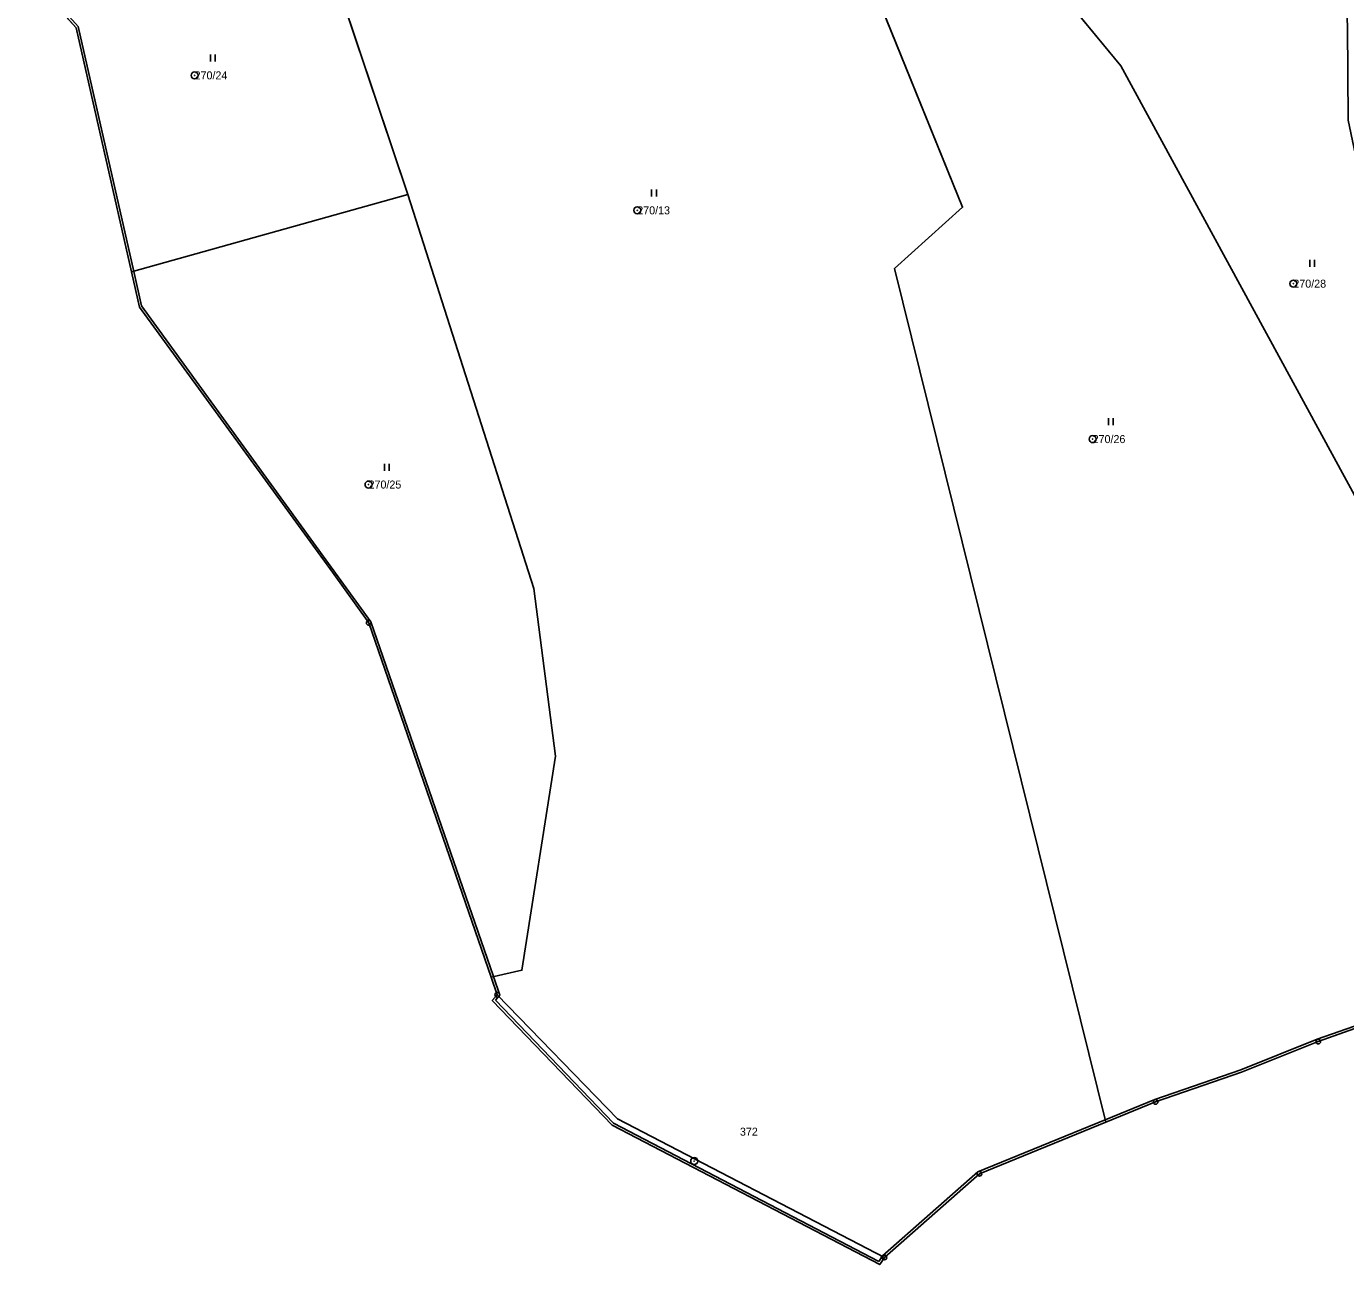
# Model space of a CAD drawing. Extents: x -652854 to -650068, y -1097661 to -1095417.
# Drawn here: x -652221.5 to -651941.1, y -1096457.9 to -1096194.7 of the extents above; entities that cross this region are included whole.
import ezdxf

# ---------------------------------------------------------------- set-up
doc = ezdxf.new("R2010")
doc.units = 0
for name, color, linetype in [('Definiční body parcel', 7, 'Continuous'), ('Geodetické body', 7, 'Continuous'), ('Hranice obcí', 7, 'Continuous'), ('Hranice parcel', 7, 'Continuous'), ('Obvody jako plochy', 7, 'Continuous'), ('Ostatní hranice', 7, 'Continuous'), ('Parcelní čísla', 7, 'Continuous'), ('Prvky pro prodl_ par_ č_', 7, 'Continuous'), ('Značky kultur', 7, 'Continuous')]:
    doc.layers.add(name, color=color, linetype=linetype)

msp = doc.modelspace()

# ---------------------------------------------------------------- linework, layer by layer
at = {"layer": 'Definiční body parcel'}
for centre, radius in [((-652185.7, -1096205.16), 0.75), ((-652185.7, -1096205.16), 0.0327), ((-652091.65, -1096233.84), 0.75), ((-652091.65, -1096233.84), 0.0327), ((-651952.24, -1096249.42), 0.75), ((-651952.24, -1096249.42), 0.0327), ((-651994.89, -1096282.46), 0.75), ((-651994.89, -1096282.46), 0.0327), ((-652148.74, -1096292.12), 0.75), ((-652148.74, -1096292.12), 0.0327), ((-652079.55, -1096435.9), 0.75), ((-652079.55, -1096435.9), 0.0327)]:
    msp.add_circle(centre, radius, dxfattribs=at)
at = {"layer": 'Geodetické body'}
for centre, radius in [((-652148.71, -1096321.51), 0.5), ((-652148.71, -1096321.51), 0.001), ((-652121.39, -1096400.54), 0.5), ((-652121.39, -1096400.54), 0.001), ((-651946.95, -1096410.49), 0.5), ((-651946.95, -1096410.49), 0.001), ((-651981.51, -1096423.32), 0.5), ((-651981.51, -1096423.32), 0.001), ((-652018.96, -1096438.6), 0.5), ((-652018.96, -1096438.6), 0.001), ((-652039.13, -1096456.38), 0.5), ((-652039.13, -1096456.38), 0.001)]:
    msp.add_circle(centre, radius, dxfattribs=at)
at = {"layer": 'Hranice obcí'}
for p, q in [((-652210.9, -1096195.04), (-652221.45, -1096183.25)), ((-652199.14, -1096246.92), (-652210.9, -1096195.04)), ((-652197.44, -1096254.42), (-652199.14, -1096246.92)), ((-652156.44, -1096310.73), (-652197.44, -1096254.42)), ((-652148.71, -1096321.51), (-652156.44, -1096310.73)), ((-652122.68, -1096396.82), (-652148.71, -1096321.51)), ((-652121.39, -1096400.54), (-652122.68, -1096396.82)), ((-652122.45, -1096401.76), (-652121.39, -1096400.54)), ((-651915.68, -1096399.4), (-651946.95, -1096410.49)), ((-652096.98, -1096428.27), (-652122.45, -1096401.76)), ((-651946.95, -1096410.49), (-651963.26, -1096417)), ((-651963.26, -1096417), (-651981.51, -1096423.32)), ((-651981.51, -1096423.32), (-651992.07, -1096427.63)), ((-652040.14, -1096457.91), (-652096.98, -1096428.27)), ((-651992.07, -1096427.63), (-652018.96, -1096438.6)), ((-652018.96, -1096438.6), (-652039.13, -1096456.38)), ((-652039.13, -1096456.38), (-652040.14, -1096457.91))]:
    msp.add_line(p, q, dxfattribs=at)
at = {"layer": 'Hranice parcel'}
for p, q in [((-652057.53, -1096119.89), (-651988.88, -1096203.13)), ((-652066.96, -1096123.51), (-652022.53, -1096233.18)), ((-652163.72, -1096161.03), (-652140.38, -1096230.48)), ((-651988.88, -1096203.13), (-651935.29, -1096301.66)), ((-652140.38, -1096230.48), (-652199.14, -1096246.92)), ((-652140.38, -1096230.48), (-652113.66, -1096314.2)), ((-652022.53, -1096233.18), (-652036.99, -1096246.19)), ((-652036.99, -1096246.19), (-651992.07, -1096427.63)), ((-652113.66, -1096314.2), (-652109.04, -1096349.86)), ((-652109.04, -1096349.86), (-652116.16, -1096395.34)), ((-652116.16, -1096395.34), (-652122.68, -1096396.82)), ((-652121.39, -1096400.54), (-652095.82, -1096426.92)), ((-652095.82, -1096426.92), (-652039.13, -1096456.38))]:
    msp.add_line(p, q, dxfattribs=at)
at = {"layer": 'Obvody jako plochy'}
for points in [[(-652047.62, -1096116.05), (-652057.53, -1096119.89), (-651988.88, -1096203.13), (-651935.29, -1096301.66), (-651889.71, -1096389.26), (-651881.07, -1096385.89), (-651862.37, -1096368.4), (-651859.22, -1096330.24), (-651863.16, -1096325.62), (-651893.8, -1096290.17), (-651915.5, -1096264.18), (-651935.12, -1096240.7), (-651940.57, -1096214.69), (-651940.73, -1096194.74), (-651941.55, -1096176.41), (-651982.15, -1096156.91), (-652010.08, -1096146.47), (-652028.17, -1096124.39)], [(-652057.53, -1096119.89), (-652066.96, -1096123.51), (-652022.53, -1096233.18), (-652036.99, -1096246.19), (-651992.07, -1096427.63), (-651981.51, -1096423.32), (-651963.26, -1096417), (-651946.95, -1096410.49), (-651915.68, -1096399.4), (-651889.71, -1096389.26), (-651935.29, -1096301.66), (-651988.88, -1096203.13)], [(-652066.96, -1096123.51), (-652163.72, -1096161.03), (-652140.38, -1096230.48), (-652113.66, -1096314.2), (-652109.04, -1096349.86), (-652116.16, -1096395.34), (-652122.68, -1096396.82), (-652121.39, -1096400.54), (-652095.82, -1096426.92), (-652039.13, -1096456.38), (-652018.96, -1096438.6), (-651992.07, -1096427.63), (-652036.99, -1096246.19), (-652022.53, -1096233.18)], [(-652163.72, -1096161.03), (-652221.45, -1096183.25), (-652210.9, -1096195.04), (-652199.14, -1096246.92), (-652140.38, -1096230.48)], [(-652197.44, -1096254.42), (-652156.44, -1096310.73), (-652148.71, -1096321.51), (-652122.68, -1096396.82), (-652116.16, -1096395.34), (-652109.04, -1096349.86), (-652113.66, -1096314.2), (-652140.38, -1096230.48), (-652199.14, -1096246.92)], [(-652121.39, -1096400.54), (-652122.45, -1096401.76), (-652096.98, -1096428.27), (-652040.14, -1096457.91), (-652039.13, -1096456.38), (-652095.82, -1096426.92)]]:
    msp.add_lwpolyline(points, close=True, dxfattribs=at)
at = {"layer": 'Ostatní hranice'}
for p, q in [((-652210.48, -1096194.75), (-652221.05, -1096182.93)), ((-652198.64, -1096246.85), (-652210.48, -1096194.75)), ((-652197, -1096254.17), (-652198.64, -1096246.85)), ((-652148.26, -1096321.27), (-652197, -1096254.17)), ((-652122.2, -1096396.66), (-652148.26, -1096321.27)), ((-652120.86, -1096400.61), (-652122.2, -1096396.66)), ((-651915.84, -1096398.91), (-651947.15, -1096410.02)), ((-652121.78, -1096401.74), (-652120.86, -1096400.61)), ((-652096.68, -1096427.86), (-652121.78, -1096401.74)), ((-651947.15, -1096410.02), (-651963.43, -1096416.53)), ((-651963.43, -1096416.53), (-651981.7, -1096422.85)), ((-651981.7, -1096422.85), (-651992.26, -1096427.17)), ((-652040.32, -1096457.25), (-652096.68, -1096427.86)), ((-651992.26, -1096427.17), (-652019.26, -1096438.19)), ((-652019.26, -1096438.19), (-652039.51, -1096456.04)), ((-652039.51, -1096456.04), (-652040.32, -1096457.25))]:
    msp.add_line(p, q, dxfattribs=at)
at = {"layer": 'Značky kultur'}
for p, q in [((-652182.357, -1096200.725), (-652182.357, -1096202.225)), ((-652181.335, -1096202.225), (-652181.335, -1096200.725)), ((-652088.607, -1096229.405), (-652088.607, -1096230.905)), ((-652087.585, -1096230.905), (-652087.585, -1096229.405)), ((-651948.767, -1096244.365), (-651948.767, -1096245.865)), ((-651947.745, -1096245.865), (-651947.745, -1096244.365)), ((-651991.547, -1096278.025), (-651991.547, -1096279.525)), ((-651990.525, -1096279.525), (-651990.525, -1096278.025)), ((-652145.357, -1096287.685), (-652145.357, -1096289.185)), ((-652144.335, -1096289.185), (-652144.335, -1096287.685))]:
    msp.add_line(p, q, dxfattribs=at)

# ---------------------------------------------------------------- texts
at = {"layer": 'Parcelní čísla'}
for s, height, p in [('270/24', 1.7, (-652185.7, -1096206.01)), ('270/13', 1.7, (-652091.65, -1096234.69)), ('270/28', 1.7, (-651952.24, -1096250.27)), ('270/26', 1.7, (-651994.89, -1096283.31)), ('270/25', 1.7, (-652148.74, -1096292.97)), ('372', 0.1, (-652079.55, -1096435.9))]:
    msp.add_text(s, height=height, dxfattribs=at).set_placement(p)
at = {"layer": 'Prvky pro prodl_ par_ č_'}
msp.add_text('372', height=1.7, dxfattribs=at).set_placement((-652069.83, -1096430.51))

doc.saveas('drawing.dxf')
